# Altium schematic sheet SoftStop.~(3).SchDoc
size A
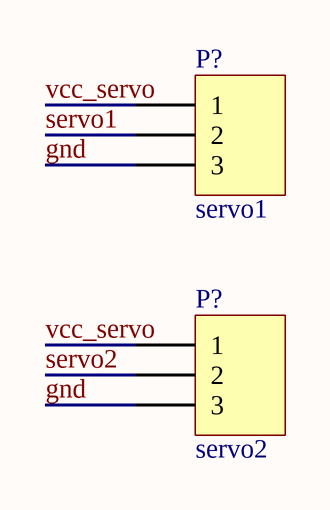
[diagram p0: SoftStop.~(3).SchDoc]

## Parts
(Parts that share a designator on the sheet are numbered #1, #2 ... from top to bottom, then left to right.)
P?#1  servo1  [HDR1X3H]
P?#2  servo2  [HDR1X3H]

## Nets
gnd: P?#1.3 P?#2.3
servo1: P?#1.2
servo2: P?#2.2
vcc_servo: P?#1.1 P?#2.1

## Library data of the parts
P?#1 P?#2 = Header 3H: Header, 3-Pin, Right Angle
